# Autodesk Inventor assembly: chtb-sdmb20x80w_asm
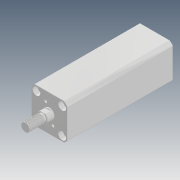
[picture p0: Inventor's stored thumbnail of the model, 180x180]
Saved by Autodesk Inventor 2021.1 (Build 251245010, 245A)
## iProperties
Company: Microsoft
Created: 2018-05
Part Number: chtb-sdmb20x80w_asm
Description: STEP AP214
Document SubType Name: Assembly
Designer: user
Title: chtb-sdmb20x80w_asm.STEP
Author: Windows
Revision Number: ÈÎºÎ
Sending System: SolidWorks 2015
Preprocessor: SwSTEP 2.0
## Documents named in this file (4)
- D:\Vault_2016\Projekty\Clamptek\Hydraulic\CHTB\CHTB-20\Inventor\CHTB-SDMB20x80W\chtb-sdmb20x80w_asm.iam
- D:\Vault_2016\Projekty\Clamptek\Hydraulic\CHTB\CHTB-20\Inventor\CHTB-SDMB20x80W\CHTB-SDMB20X80NBT.ipt
- D:\Vault_2016\Projekty\Clamptek\Hydraulic\CHTB\CHTB-20\Inventor\CHTB-SDMB20x80W\CHTB-SDMB20X80WHSG.ipt
- D:\Vault_2016\Projekty\Clamptek\Hydraulic\CHTB\CHTB-20\Inventor\CHTB-SDMB20x80W\QG_3.ipt
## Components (3 placed, 3 different names)
1. CHTB-SDMB20X80NBT_1
2. CHTB-SDMB20X80WHSG_2
3. QG_3_3
